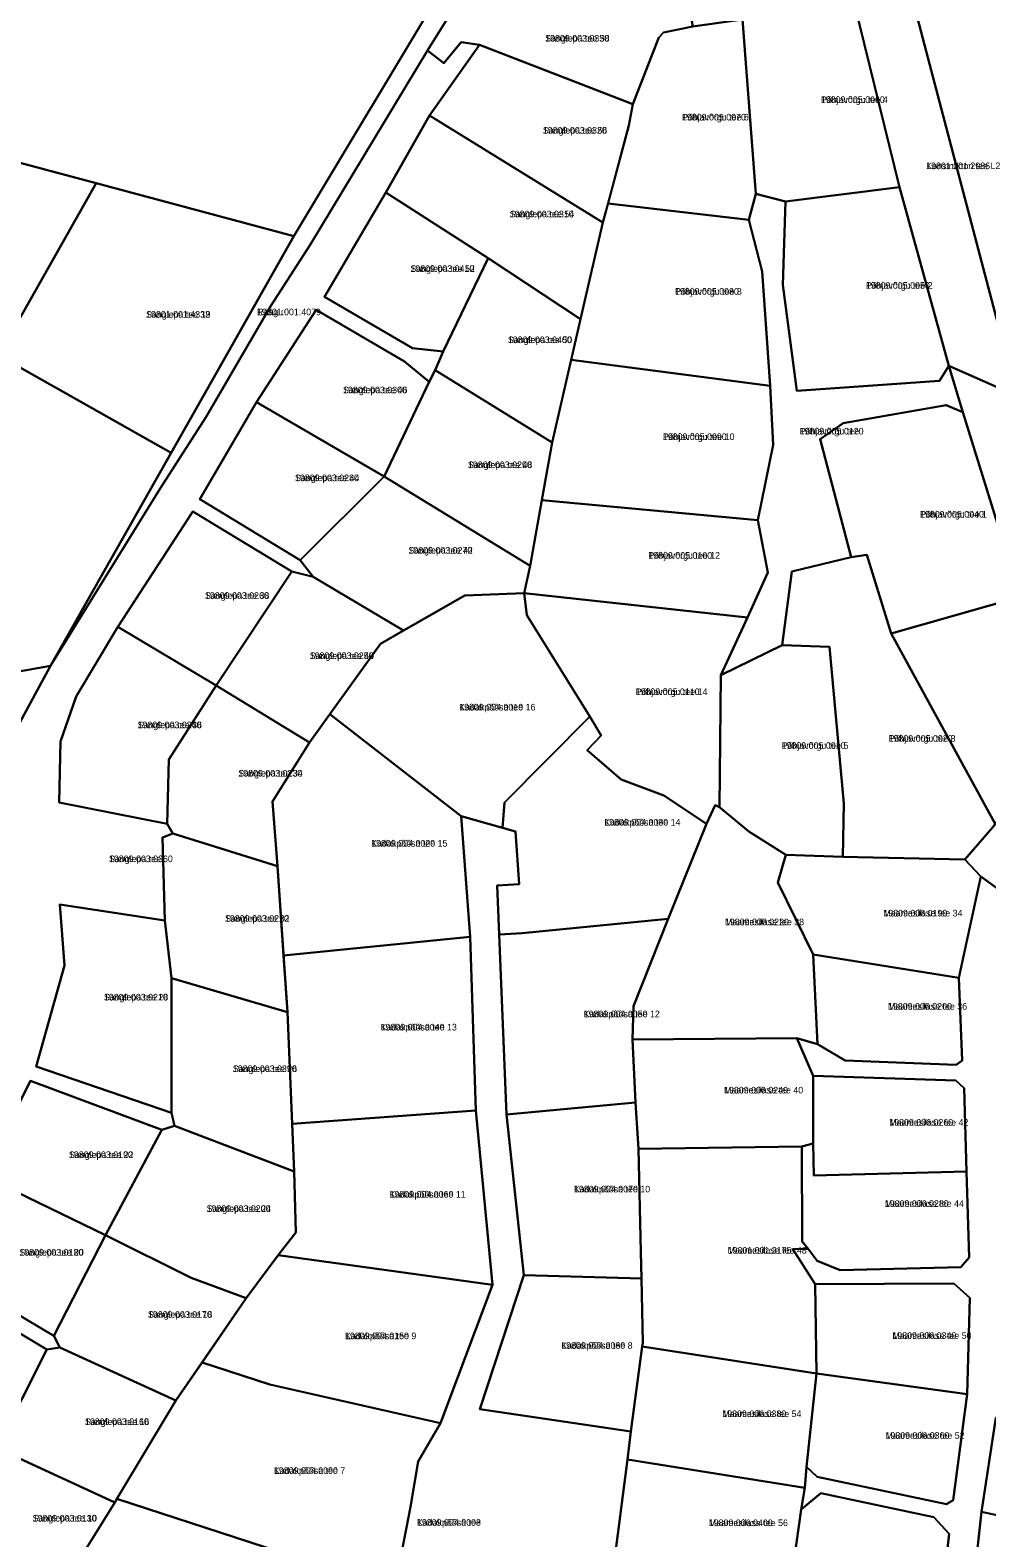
# Model space of a CAD drawing. Extents: x 516875 to 535633, y 6574491 to 6593094.
# Drawn here: x 520836.7 to 521053.8, y 6589652.4 to 6589994.6 of the extents above; entities that cross this region are included whole.
import ezdxf

# ---------------------------------------------------------------- set-up
doc = ezdxf.new("R2010")
doc.units = 0
for name, color, linetype in [('L_AADRESS', 7, 'Continuous'), ('PIIR', 7, 'Continuous'), ('TUNNUS', 7, 'Continuous')]:
    doc.layers.add(name, color=color, linetype=linetype)

msp = doc.modelspace()

# ---------------------------------------------------------------- linework, layer by layer
at = {"layer": 'PIIR'}
for points in [[(521212.93, 6590426.56), (521211.23, 6590395.26), (521269.5, 6590395.98), (521237.36, 6590297.46), (521251.86, 6590152.22), (521285.8, 6589812.42), (521060.68, 6589911.6), (521034.69, 6590010.38), (521025.13, 6590014.52), (520989.29, 6590011.02), (520988.61, 6590073.5), (520991.67, 6590073.59), (521039.51, 6590073.51), (521027.49, 6590232.1), (521034.16, 6590249.09), (521036.23, 6590253.5), (521038.39, 6590257.74), (521039.01, 6590259.29), (521041.98, 6590266.66), (521045.7, 6590275.91), (521086.85, 6590378.08), (521089.67, 6590385.09), (521115.52, 6590449.29)], [(520830.79, 6589830.84), (520841.36, 6589850.29), (520866.24, 6589890.56), (520876.63, 6589906.83), (520891.31, 6589932.04), (520900.25, 6589945.86), (520926.88, 6589989.96), (520930.59, 6589987.09), (520934.5, 6589991.88), (520938.71, 6589991.28), (520927.33, 6589975.25), (520917.43, 6589957.79), (520903.54, 6589934.06), (520923.48, 6589922.4), (520930.44, 6589921.69), (520928.67, 6589917.4), (520927.25, 6589914.77), (520921.7, 6589919.37), (520901.66, 6589931.11), (520888.11, 6589910.16), (520875.24, 6589888.12), (520898.01, 6589874.3), (520900.98, 6589870.53), (520896.13, 6589871.71), (520873.66, 6589885.34), (520856.62, 6589859.19), (520847.16, 6589843.37), (520843.57, 6589833.15), (520843.29, 6589819.32), (520867.83, 6589814.44), (520869.08, 6589812.28), (520866.76, 6589811.34), (520867.3, 6589792.51), (520843.43, 6589796.12), (520844.47, 6589782.3), (520838.08, 6589759.35), (520868.8, 6589748.84), (520869.48, 6589745.92), (520866.63, 6589744.96), (520836.81, 6589756.1), (520825.8, 6589734.61)], [(521061.38, 6589865.96), (521048.39, 6589907.9), (521045.2, 6589918.42), (521060.68, 6589911.6)], [(520921.16, 6589649.61), (520923.07, 6589659.41), (520924.75, 6589669.66), (520929.83, 6589678.39), (520941.64, 6589709.79), (520937.87, 6589749.39), (520936.54, 6589788.76), (520934.55, 6589816.16), (520943.92, 6589813.55), (520946.83, 6589812.74), (520947.7, 6589800.77), (520942.69, 6589800.41), (520943.15, 6589789.32), (520944.83, 6589748.5), (520948.78, 6589711.96), (520938.8, 6589681.54), (520973.04, 6589676.49), (520972.3, 6589670.14), (520969.02, 6589644.99)], [(521043.32, 6589636.03), (521045.26, 6589653.3), (521041.83, 6589657.04), (521016.16, 6589662.54), (521011.67, 6589658.79), (521012.52, 6589663.75), (521012.92, 6589668.51), (521015.37, 6589666.23), (521044.72, 6589660.04), (521046.22, 6589660.88), (521049.4, 6589684.96), (521049.96, 6589706.84), (521046.38, 6589710.1), (521014.9, 6589709.93), (521009.82, 6589717.87), (521013.26, 6589717.98), (521015.31, 6589715.23), (521020.52, 6589713.1), (521047.92, 6589713.78), (521049.83, 6589716.02), (521049.25, 6589735.51), (521048.72, 6589754.44), (521046.79, 6589756.2), (521014.42, 6589757.23), (521010.75, 6589765.79), (521015.42, 6589764.41), (521021.71, 6589760.74), (521046.91, 6589759.71), (521048.28, 6589760.7), (521047.5, 6589779.45), (521052.45, 6589802.46), (521070.1, 6589789.68)], [(520815.83, 6589713.79), (520842.1, 6589698.25), (520843.48, 6589695.59), (520840.52, 6589695.13), (520813.76, 6589711.07)]]:
    msp.add_lwpolyline(points, dxfattribs=at)
for points in [[(520801.74, 6589973.23), (520824.96, 6590069.29), (520912.31, 6590071.54), (520912.53, 6590070.3), (520912.35, 6590047.34), (520912.17, 6590025.02), (520931.67, 6590006.39), (520896.53, 6589947.83), (520851.66, 6589959.86)], [(521034.69, 6590010.38), (521060.68, 6589911.6), (521045.2, 6589918.42), (521034, 6589958.97), (521023.82, 6590000.49), (520998.37, 6589997.05), (520987.11, 6589995.47), (520985.78, 6590002.75), (520989.36, 6590004.84), (520989.29, 6590011.02), (521025.13, 6590014.52)], [(520652.47, 6590013.72), (520656.14, 6590012.73), (520801.74, 6589973.23), (520851.66, 6589959.86), (520829.51, 6589920.73), (520868.75, 6589898.67), (520841.36, 6589850.29), (520795.36, 6589842.1), (520755.36, 6589834.88), (520730.05, 6589830.47), (520727.75, 6589830.09), (520700.2, 6589850.72), (520669.72, 6589873.59), (520638.79, 6589896.75), (520609.43, 6589918.74), (520601.53, 6589924.66), (520599.13, 6589926.46)], [(520935.03, 6590003.18), (520926.88, 6589989.96), (520900.25, 6589945.86), (520891.31, 6589932.04), (520876.63, 6589906.83), (520866.24, 6589890.56), (520841.36, 6589850.29), (520868.75, 6589898.67), (520896.53, 6589947.83), (520931.67, 6590006.39)], [(520979.11, 6590006.21), (520985.78, 6590002.75), (520987.11, 6589995.47), (520980.47, 6589994.05), (520979.41, 6589992.92), (520973.5, 6589977.83), (520938.71, 6589991.28), (520934.5, 6589991.88), (520930.59, 6589987.09), (520926.88, 6589989.96), (520935.03, 6590003.18)], [(521023.82, 6590000.49), (521034, 6589958.97), (521008.17, 6589955.68), (521001.43, 6589957.44), (520998.37, 6589997.05)], [(520998.37, 6589997.05), (521001.43, 6589957.44), (520999.86, 6589951.52), (520967.88, 6589955.23), (520972.61, 6589973), (520973.5, 6589977.83), (520979.41, 6589992.92), (520980.47, 6589994.05), (520987.11, 6589995.47)], [(520973.5, 6589977.83), (520972.61, 6589973), (520966.71, 6589950.96), (520927.33, 6589975.25), (520938.71, 6589991.28)], [(520966.71, 6589950.96), (520961.59, 6589928.97), (520940.66, 6589942.86), (520917.43, 6589957.79), (520927.33, 6589975.25)], [(520829.51, 6589920.73), (520851.66, 6589959.86), (520896.53, 6589947.83), (520868.75, 6589898.67)], [(520940.66, 6589942.86), (520930.44, 6589921.69), (520923.48, 6589922.4), (520903.54, 6589934.06), (520917.43, 6589957.79)], [(521048.39, 6589907.9), (521044.65, 6589909.46), (521021.23, 6589905.38), (521015.98, 6589901.74), (521023.04, 6589874.95), (521009.58, 6589871.75), (521007.39, 6589855.01), (520993.48, 6589848.21), (520999.5, 6589861.3), (521004.13, 6589871.48), (521001.88, 6589883.38), (521005.32, 6589900.44), (521004.67, 6589913.88), (521002.86, 6589939.86), (520999.86, 6589951.52), (521001.43, 6589957.44), (521008.17, 6589955.68), (521007.57, 6589936.81), (521010.69, 6589912.73), (521043.08, 6589914.98), (521045.2, 6589918.42)], [(521045.2, 6589918.42), (521043.08, 6589914.98), (521010.69, 6589912.73), (521007.57, 6589936.81), (521008.17, 6589955.68), (521034, 6589958.97)], [(520999.86, 6589951.52), (521002.86, 6589939.86), (521004.67, 6589913.88), (520959.49, 6589919.76), (520961.59, 6589928.97), (520966.71, 6589950.96), (520967.88, 6589955.23)], [(520961.59, 6589928.97), (520955.22, 6589901.03), (520928.67, 6589917.4), (520930.44, 6589921.69), (520940.66, 6589942.86)], [(520921.7, 6589919.37), (520927.25, 6589914.77), (520917.04, 6589893.27), (520888.11, 6589910.16), (520901.66, 6589931.11)], [(521004.67, 6589913.88), (521005.32, 6589900.44), (521001.88, 6589883.38), (520952.86, 6589887.94), (520955.22, 6589901.03), (520959.49, 6589919.76)], [(520955.22, 6589901.03), (520952.86, 6589887.94), (520950.17, 6589873), (520917.04, 6589893.27), (520927.25, 6589914.77), (520928.67, 6589917.4)], [(520917.04, 6589893.27), (520898.01, 6589874.3), (520875.24, 6589888.12), (520888.11, 6589910.16)], [(521015.98, 6589901.74), (521021.23, 6589905.38), (521044.65, 6589909.46), (521048.39, 6589907.9), (521061.38, 6589865.96), (521032.12, 6589857.66), (521026.59, 6589875.47), (521023.04, 6589874.95)], [(520950.17, 6589873), (520948.8, 6589866.8), (520935.36, 6589866.25), (520921.43, 6589858.31), (520900.98, 6589870.53), (520898.01, 6589874.3), (520917.04, 6589893.27)], [(521001.88, 6589883.38), (521004.13, 6589871.48), (520999.5, 6589861.3), (520948.8, 6589866.8), (520950.17, 6589873), (520952.86, 6589887.94)], [(520896.13, 6589871.71), (520878.89, 6589845.84), (520856.62, 6589859.19), (520873.66, 6589885.34)], [(521009.58, 6589871.75), (521023.04, 6589874.95), (521026.59, 6589875.47), (521032.12, 6589857.66), (521055.75, 6589814.41), (521055.2, 6589813.68), (521048.88, 6589806.35), (521021.13, 6589806.97), (521021.4, 6589819.06), (521018.12, 6589854.64), (521007.39, 6589855.01)], [(520900.98, 6589870.53), (520921.43, 6589858.31), (520916.21, 6589855.3), (520904.72, 6589839.34), (520900.1, 6589832.92), (520878.89, 6589845.84), (520896.13, 6589871.71)], [(520916.21, 6589855.3), (520921.43, 6589858.31), (520935.36, 6589866.25), (520948.8, 6589866.8), (520949.47, 6589861.78), (520963.74, 6589838.79), (520944.39, 6589819.31), (520943.92, 6589813.55), (520934.55, 6589816.16), (520904.72, 6589839.34)], [(520999.5, 6589861.3), (520993.48, 6589848.21), (520993.14, 6589818.25), (520992.22, 6589818.7), (520990.25, 6589814.48), (520980.56, 6589820.9), (520970.87, 6589824.54), (520963.13, 6589831.18), (520966.32, 6589834.46), (520963.74, 6589838.79), (520949.47, 6589861.78), (520948.8, 6589866.8)], [(521079.76, 6589840.33), (521073.53, 6589836.38), (521055.75, 6589814.41), (521032.12, 6589857.66), (521061.38, 6589865.96)], [(520878.89, 6589845.84), (520868.2, 6589829.07), (520867.83, 6589814.44), (520843.29, 6589819.32), (520843.57, 6589833.15), (520847.16, 6589843.37), (520856.62, 6589859.19)], [(521007.39, 6589855.01), (521018.12, 6589854.64), (521021.4, 6589819.06), (521021.13, 6589806.97), (521008.21, 6589807.39), (520999.82, 6589812.74), (520993.14, 6589818.25), (520993.48, 6589848.21)], [(520841.36, 6589850.29), (520830.79, 6589830.84), (520820.54, 6589813.09), (520794.65, 6589829.12), (520789.35, 6589828.12), (520791.12, 6589831.09), (520795.36, 6589842.1)], [(520900.1, 6589832.92), (520891.72, 6589819.54), (520892.81, 6589804.84), (520869.08, 6589812.28), (520867.83, 6589814.44), (520868.2, 6589829.07), (520878.89, 6589845.84)], [(521052.45, 6589802.46), (521048.88, 6589806.35), (521055.2, 6589813.68), (521073.53, 6589836.38), (521079.76, 6589840.33), (521099.37, 6589822.79), (521070.1, 6589789.68)], [(520892.81, 6589804.84), (520891.72, 6589819.54), (520900.1, 6589832.92), (520904.72, 6589839.34), (520934.55, 6589816.16), (520936.54, 6589788.76), (520894.21, 6589784.57)], [(520943.15, 6589789.32), (520942.69, 6589800.41), (520947.7, 6589800.77), (520946.83, 6589812.74), (520943.92, 6589813.55), (520944.39, 6589819.31), (520963.74, 6589838.79), (520966.32, 6589834.46), (520963.13, 6589831.18), (520970.87, 6589824.54), (520980.56, 6589820.9), (520990.25, 6589814.48), (520981.53, 6589792.86), (520948.36, 6589789.6)], [(520973.65, 6589773.09), (520981.53, 6589792.86), (520990.25, 6589814.48), (520992.22, 6589818.7), (520993.14, 6589818.25), (520999.82, 6589812.74), (521008.21, 6589807.39), (521006.42, 6589801.15), (521014.44, 6589784.8), (521015.42, 6589764.41), (521010.75, 6589765.79), (520973.4, 6589765.49)], [(520892.81, 6589804.84), (520895.09, 6589771.73), (520868.76, 6589779.41), (520867.3, 6589792.51), (520866.76, 6589811.34), (520869.08, 6589812.28)], [(521006.42, 6589801.15), (521008.21, 6589807.39), (521021.13, 6589806.97), (521048.88, 6589806.35), (521052.45, 6589802.46), (521047.5, 6589779.45), (521014.44, 6589784.8)], [(520867.3, 6589792.51), (520868.76, 6589779.41), (520868.8, 6589748.84), (520838.08, 6589759.35), (520844.47, 6589782.3), (520843.43, 6589796.12)], [(520948.36, 6589789.6), (520981.53, 6589792.86), (520973.65, 6589773.09), (520973.4, 6589765.49), (520974.1, 6589751.15), (520944.83, 6589748.5), (520943.15, 6589789.32)], [(520936.54, 6589788.76), (520937.87, 6589749.39), (520896.17, 6589746.32), (520895.09, 6589771.73), (520894.21, 6589784.57)], [(521015.42, 6589764.41), (521014.44, 6589784.8), (521047.5, 6589779.45), (521048.28, 6589760.7), (521046.91, 6589759.71), (521021.71, 6589760.74)], [(520895.09, 6589771.73), (520896.63, 6589735.53), (520869.48, 6589745.92), (520868.8, 6589748.84), (520868.76, 6589779.41)], [(520974.1, 6589751.15), (520973.4, 6589765.49), (521010.75, 6589765.79), (521014.42, 6589757.23), (521014.45, 6589741.9), (521011.88, 6589741.2), (520974.81, 6589740.69)], [(520866.63, 6589744.96), (520853.82, 6589721.06), (520825.8, 6589734.61), (520836.81, 6589756.1)], [(521014.45, 6589741.9), (521014.42, 6589757.23), (521046.79, 6589756.2), (521048.72, 6589754.44), (521049.25, 6589735.51), (521014.57, 6589734.61)], [(520948.78, 6589711.96), (520944.83, 6589748.5), (520974.1, 6589751.15), (520974.81, 6589740.69), (520975.32, 6589717.24), (520975.45, 6589711.27)], [(520896.98, 6589721.68), (520896.63, 6589735.53), (520896.17, 6589746.32), (520937.87, 6589749.39), (520941.64, 6589709.79), (520893.03, 6589716.53)], [(520896.63, 6589735.53), (520896.98, 6589721.68), (520893.03, 6589716.53), (520885.76, 6589706.79), (520873.28, 6589711.35), (520853.82, 6589721.06), (520866.63, 6589744.96), (520869.48, 6589745.92)], [(520975.32, 6589717.24), (520974.81, 6589740.69), (521011.88, 6589741.2), (521011.9, 6589719.61), (521013.26, 6589717.98), (521009.82, 6589717.87), (521014.9, 6589709.93), (521015.21, 6589689.66), (520975.6, 6589695.81), (520975.75, 6589696.61), (520975.45, 6589711.27)], [(521015.31, 6589715.23), (521013.26, 6589717.98), (521011.9, 6589719.61), (521011.88, 6589741.2), (521014.45, 6589741.9), (521014.57, 6589734.61), (521049.25, 6589735.51), (521049.83, 6589716.02), (521047.92, 6589713.78), (521020.52, 6589713.1)], [(520853.82, 6589721.06), (520842.1, 6589698.25), (520815.83, 6589713.79), (520825.8, 6589734.61)], [(520873.28, 6589711.35), (520885.76, 6589706.79), (520869.79, 6589683.57), (520843.48, 6589695.59), (520842.1, 6589698.25), (520853.82, 6589721.06)], [(520875.75, 6589692.2), (520885.76, 6589706.79), (520893.03, 6589716.53), (520941.64, 6589709.79), (520929.83, 6589678.39), (520891.12, 6589687.2)], [(520840.52, 6589695.13), (520829.16, 6589672.69), (520800.95, 6589685.54), (520813.76, 6589711.07)], [(520948.78, 6589711.96), (520975.45, 6589711.27), (520975.75, 6589696.61), (520975.6, 6589695.81), (520973.04, 6589676.49), (520938.8, 6589681.54)], [(521014.9, 6589709.93), (521046.38, 6589710.1), (521049.96, 6589706.84), (521049.4, 6589684.96), (521015.21, 6589689.66)], [(520843.48, 6589695.59), (520869.79, 6589683.57), (520856.41, 6589661.21), (520855.91, 6589660.36), (520829.16, 6589672.69), (520840.52, 6589695.13)], [(520973.04, 6589676.49), (520975.6, 6589695.81), (521015.21, 6589689.66), (521012.92, 6589668.51), (521012.52, 6589663.75), (520972.3, 6589670.14)], [(520869.79, 6589683.57), (520875.75, 6589692.2), (520891.12, 6589687.2), (520929.83, 6589678.39), (520924.75, 6589669.66), (520923.07, 6589659.41), (520921.16, 6589649.61), (520916.72, 6589641.58), (520856.41, 6589661.21)], [(521015.21, 6589689.66), (521049.4, 6589684.96), (521046.22, 6589660.88), (521044.72, 6589660.04), (521015.37, 6589666.23), (521012.92, 6589668.51)], [(521049.66, 6589631.37), (521044.4, 6589588.09), (521061.04, 6589578.44), (521085.2, 6589607.75), (521108.8, 6589636.02), (521132.35, 6589663.43), (521099.43, 6589671.23), (521058.55, 6589680.33), (521055.9, 6589679.58), (521052.61, 6589658.28)], [(521055.9, 6589679.58), (521058.55, 6589680.33), (521099.43, 6589671.23), (521087.06, 6589650.84), (521052.61, 6589658.28)], [(520855.91, 6589660.36), (520842.95, 6589639.45), (520818.25, 6589646.57), (520818.41, 6589649.98), (520829.16, 6589672.69)], [(520972.3, 6589670.14), (521012.52, 6589663.75), (521011.67, 6589658.79), (521009.09, 6589639.91), (520969.02, 6589644.99)], [(521011.67, 6589658.79), (521016.16, 6589662.54), (521041.83, 6589657.04), (521045.26, 6589653.3), (521043.32, 6589636.03), (521009.09, 6589639.91)], [(520848.23, 6589619.63), (520837.67, 6589625.02), (520842.95, 6589639.45), (520855.91, 6589660.36), (520856.41, 6589661.21), (520916.72, 6589641.58), (520899.97, 6589609.1)], [(521052.61, 6589658.28), (521087.06, 6589650.84), (521067.9, 6589619.91), (521049.66, 6589631.37)]]:
    msp.add_lwpolyline(points, close=True, dxfattribs=at)

# ---------------------------------------------------------------- texts
at = {"layer": 'L_AADRESS'}
for s, p in [('Sanglepa tee 58', (520953.6, 6589992.02)), ('Põhjavõrgu tee 4', (521016.18, 6589978.08)), ('Põhjavõrgu tee 6', (520984.66, 6589974.11)), ('Sanglepa tee 56', (520953.07, 6589971.12)), ('Konstruktori tee L2', (521040.07, 6589963.06)), ('Sanglepa tee 54', (520945.56, 6589952.11)), ('Sanglepa tee 52', (520923.01, 6589939.74)), ('Põhjavõrgu tee 8', (520983.06, 6589934.55)), ('Põhjavõrgu tee 2', (521026.39, 6589935.91)), ('Sanglepa tee 19', (520863.02, 6589929.35)), ('Räägu', (520888.2, 6589929.89)), ('Sanglepa tee 50', (520945.13, 6589923.57)), ('Sanglepa tee 46', (520907.72, 6589912.19)), ('Põhjavõrgu tee 10', (520980.3, 6589901.57)), ('Põhjavõrgu tee', (521011.37, 6589902.83)), ('Sanglepa tee 48', (520936.06, 6589895.2)), ('Sanglepa tee 44', (520896.82, 6589892.23)), ('Põhjavõrgu tee 1', (521038.68, 6589883.97)), ('Sanglepa tee 42', (520922.56, 6589875.79)), ('Põhjavõrgu tee 12', (520977, 6589874.62)), ('Sanglepa tee 38', (520876.38, 6589865.52)), ('Sanglepa tee 40', (520900.16, 6589851.87)), ('Põhjavõrgu tee 14', (520974.15, 6589843.68)), ('Kadakpõõsa tee 16', (520934.1, 6589840.18)), ('Sanglepa tee 36', (520861.09, 6589836.15)), ('Põhjavõrgu tee 5', (521007.27, 6589831.47)), ('Põhjavõrgu tee 3', (521031.57, 6589833.08)), ('Sanglepa tee 34', (520883.96, 6589825.18)), ('Kadakpõõsa tee 14', (520967.02, 6589814.05)), ('Kadakpõõsa tee 15', (520914.13, 6589809.28)), ('Sanglepa tee', (520854.59, 6589805.75)), ('Sanglepa tee 32', (520880.93, 6589792.21)), ('Maamesilase tee 38', (520994.41, 6589791.43)), ('Maamesilase tee 34', (521030.36, 6589793.42)), ('Sanglepa tee 28', (520853.44, 6589774.35)), ('Kadakpõõsa tee 12', (520962.34, 6589770.53)), ('Maamesilase tee 36', (521031.42, 6589772.26)), ('Kadakpõõsa tee 13', (520916.26, 6589767.54)), ('Sanglepa tee 26', (520882.7, 6589758.1)), ('Maamesilase tee 40', (520994.21, 6589753.24)), ('Maamesilase tee 42', (521031.7, 6589745.92)), ('Sanglepa tee 22', (520845.52, 6589738.58)), ('Kadakpõõsa tee 11', (520918.27, 6589729.59)), ('Kadakpõõsa tee 10', (520960.14, 6589730.78)), ('Sanglepa tee 24', (520876.76, 6589726.36)), ('Maamesilase tee 44', (521030.69, 6589727.5)), ('Sanglepa tee 20', (520834.27, 6589716.43)), ('Maamesilase tee 48', (520995.01, 6589716.88)), ('Sanglepa tee 18', (520863.44, 6589702.32)), ('Kadakpõõsa tee 9', (520908.18, 6589697.46)), ('Kadakpõõsa tee 8', (520957.27, 6589695.28)), ('Maamesilase tee 50', (521032.41, 6589697.53)), ('Sanglepa tee 16', (520849.14, 6589677.98)), ('Maamesilase tee 54', (520993.81, 6589679.78)), ('Maamesilase tee 52', (521030.84, 6589674.85)), ('Kadakpõõsa tee 7', (520892.05, 6589666.89)), ('Sanglepa tee 10', (520837.27, 6589656.07)), ('Kadakpõõsa tee', (520924.51, 6589655.11)), ('Maamesilase tee 56', (520990.74, 6589655.03))]:
    msp.add_text(s, height=1.5, dxfattribs=at).set_placement(p)
at = {"layer": 'TUNNUS'}
for s, p in [('19809:003:0330', (520953.6, 6589992.02)), ('19809:005:0060', (521016.18, 6589978.08)), ('19809:005:0070', (520984.66, 6589974.11)), ('19809:003:0320', (520953.07, 6589971.12)), ('19801:001:2986', (521040.07, 6589963.06)), ('19809:003:0310', (520945.56, 6589952.11)), ('19809:003:0410', (520923.01, 6589939.74)), ('19809:005:0080', (520983.06, 6589934.55)), ('19809:005:0050', (521026.39, 6589935.91)), ('19801:001:4332', (520863.02, 6589929.35)), ('19801:001:4079', (520888.2, 6589929.89)), ('19809:003:0400', (520945.13, 6589923.57)), ('19809:003:0300', (520907.72, 6589912.19)), ('19809:005:0090', (520980.3, 6589901.57)), ('19809:005:0120', (521011.37, 6589902.83)), ('19809:003:0290', (520936.06, 6589895.2)), ('19809:003:0280', (520896.82, 6589892.23)), ('19809:005:0040', (521038.68, 6589883.97)), ('19809:003:0270', (520922.56, 6589875.79)), ('19809:005:0100', (520977, 6589874.62)), ('19809:003:0260', (520876.38, 6589865.52)), ('19809:003:0250', (520900.16, 6589851.87)), ('19809:005:0110', (520974.15, 6589843.68)), ('19809:004:0010', (520934.1, 6589840.18)), ('19809:003:0240', (520861.09, 6589836.15)), ('19809:005:0010', (521007.27, 6589831.47)), ('19809:005:0020', (521031.57, 6589833.08)), ('19809:003:0230', (520883.96, 6589825.18)), ('19809:004:0030', (520967.02, 6589814.05)), ('19809:004:0020', (520914.13, 6589809.28)), ('19809:003:0360', (520854.59, 6589805.75)), ('19809:003:0220', (520880.93, 6589792.21)), ('19809:006:0220', (520994.41, 6589791.43)), ('19809:006:0190', (521030.36, 6589793.42)), ('19809:003:0210', (520853.44, 6589774.35)), ('19809:004:0050', (520962.34, 6589770.53)), ('19809:006:0200', (521031.42, 6589772.26)), ('19809:004:0040', (520916.26, 6589767.54)), ('19809:003:0390', (520882.7, 6589758.1)), ('19809:006:0240', (520994.21, 6589753.24)), ('19809:006:0260', (521031.7, 6589745.92)), ('19809:003:0190', (520845.52, 6589738.58)), ('19809:004:0060', (520918.27, 6589729.59)), ('19809:004:0070', (520960.14, 6589730.78)), ('19809:003:0200', (520876.76, 6589726.36)), ('19809:006:0280', (521030.69, 6589727.5)), ('19809:003:0180', (520834.27, 6589716.43)), ('19801:001:3175', (520995.01, 6589716.88)), ('19809:003:0170', (520863.44, 6589702.32)), ('19809:004:0150', (520908.18, 6589697.46)), ('19809:004:0080', (520957.27, 6589695.28)), ('19809:006:0340', (521032.41, 6589697.53)), ('19809:003:0160', (520849.14, 6589677.98)), ('19809:006:0380', (520993.81, 6589679.78)), ('19809:006:0360', (521030.84, 6589674.85)), ('19809:004:0090', (520892.05, 6589666.89)), ('19809:003:0130', (520837.27, 6589656.07)), ('19809:004:0003', (520924.51, 6589655.11)), ('19809:006:0400', (520990.74, 6589655.03))]:
    msp.add_text(s, height=1.5, dxfattribs=at).set_placement(p)

doc.saveas('drawing.dxf')
